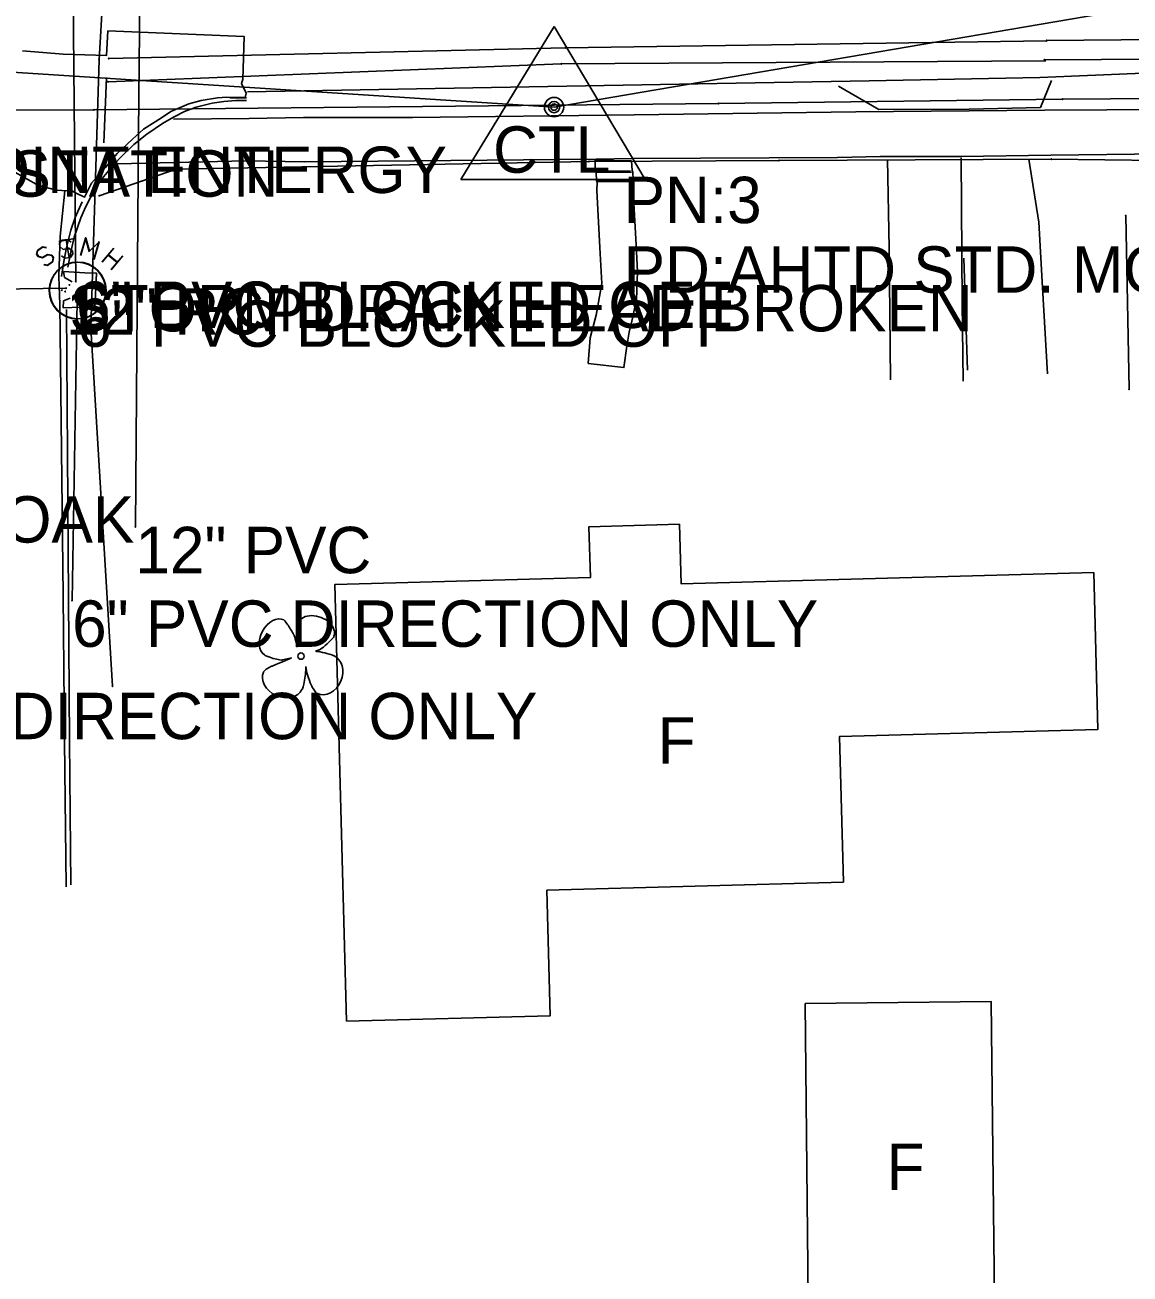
# Model space of a CAD drawing. Extents: x 1304270 to 1306561, y 1876019 to 1876752.
# Drawn here: x 1305936.2 to 1306055.3, y 1876265.9 to 1876400.4 of the extents above; entities that cross this region are included whole.
import ezdxf

# ---------------------------------------------------------------- set-up
doc = ezdxf.new("R2010")
doc.units = 0
for name, color, linetype in [('Default', 7, 'Continuous'), ('S_BUILDING', 7, 'Continuous'), ('S_BUILDING_ANNOT', 7, 'Continuous'), ('S_CURB', 7, 'Continuous'), ('S_DRG_PT_SYM', 7, 'Continuous'), ('S_DRIVEWAY', 7, 'Continuous'), ('S_EDGE_CONCRETE', 7, 'Continuous'), ('S_EDGE_PAVEMENT', 7, 'Continuous'), ('S_FENCE', 7, 'Continuous'), ('S_FIBER_OPTIC_CABLE', 7, 'Continuous'), ('S_GAS_UTILITIES', 7, 'Continuous'), ('S_MANHOLE', 7, 'Continuous'), ('S_MISC_STRUCTURES_ANNOT', 7, 'Continuous'), ('S_MSC_PT_SYM', 7, 'Continuous'), ('S_PRIMARY_CTL', 7, 'Continuous'), ('S_PRIMARY_CTL_ANNOT', 7, 'Continuous'), ('S_SIDEWALK', 7, 'Continuous'), ('S_STORM_SEWER', 7, 'Continuous'), ('S_STORM_SEWER_ANNOT', 7, 'Continuous'), ('S_SURVEY_TEXT_ANNOT', 7, 'Continuous'), ('S_TREE', 7, 'Continuous'), ('S_UTILITY_POLE_ANNOT', 7, 'Continuous'), ('S_UTL_PT_SYM', 7, 'Continuous'), ('S_WATER_UTILITIES', 7, 'Continuous'), ('S_WATER_UTILITIES_ANNOT', 7, 'Continuous')]:
    doc.layers.add(name, color=color, linetype=linetype)

msp = doc.modelspace()

# ---------------------------------------------------------------- linework, layer by layer
at = {"layer": 'Default'}
for p, q in [((1305993.25, 1876391.55), (1306312.09, 1876445.88)), ((1305473.53, 1876424.94), (1305993.25, 1876391.55))]:
    msp.add_line(p, q, dxfattribs=at)
at = {"layer": 'S_BUILDING'}
for points in [[(1306024.44, 1876308.05), (1305992.48, 1876307.19), (1305992.84, 1876293.68), (1305970.9, 1876293.09), (1305969.63, 1876340.14), (1305997.16, 1876340.88), (1305997.01, 1876346.35), (1306006.76, 1876346.61), (1306006.93, 1876340.21), (1306051.4, 1876341.41), (1306051.85, 1876324.52), (1306024.02, 1876323.77)], [(1306020.3, 1876294.98), (1306020.68, 1876259.62), (1306040.74, 1876259.83), (1306040.36, 1876295.2)]]:
    msp.add_lwpolyline(points, close=True, dxfattribs=at)
at = {"layer": 'S_CURB'}
for points in [[(1305960.11, 1876392.26), (1305958.96, 1876392.25), (1305957.65, 1876392.15), (1305956.42, 1876391.97), (1305954.67, 1876391.54), (1305953.41, 1876391.07), (1305952.23, 1876390.48), (1305951.04, 1876389.79), (1305949.38, 1876388.65), (1305947.97, 1876387.54), (1305946.46, 1876386.05), (1305945.64, 1876385.14), (1305944.55, 1876383.85), (1305943.78, 1876382.72), (1305942.79, 1876380.85), (1305942.27, 1876379.63), (1305941.54, 1876377.55), (1305941.22, 1876376.12), (1305940.84, 1876374.32)], [(1305960.1, 1876392.54), (1305958.31, 1876392.55)], [(1305941.17, 1876307.79), (1305941.05, 1876323.28), (1305940.93, 1876338.77), (1305940.82, 1876354.25), (1305940.7, 1876369.74)]]:
    msp.add_lwpolyline(points, dxfattribs=at)
at = {"layer": 'S_DRG_PT_SYM'}
msp.add_lwpolyline([(1305940.22, 1876371.83), (1305940.22, 1876371.88), (1305940.22, 1876371.83), (1305940.17, 1876371.83), (1305940.22, 1876371.83), (1305940.22, 1876371.78), (1305940.22, 1876371.83), (1305940.27, 1876371.83)], dxfattribs=at)
at = {"layer": 'S_DRIVEWAY'}
for points in [[(1306023.91, 1876393.81), (1306028.25, 1876391.29), (1306037.96, 1876391.32), (1306045.65, 1876391.5), (1306046.86, 1876394.43)], [(1306029.18, 1876385.91), (1306029.37, 1876376.36), (1306029.5, 1876362.16)], [(1306037.33, 1876362.02), (1306037.22, 1876370.47), (1306037.11, 1876386.1)], [(1306046.43, 1876362.81), (1306045.89, 1876372.13), (1306045.49, 1876379.16), (1306044.4, 1876385.95)], [(1306037.42, 1876375.28), (1306037.79, 1876363.2)]]:
    msp.add_lwpolyline(points, dxfattribs=at)
at = {"layer": 'S_EDGE_CONCRETE'}
for points in [[(1305934.88, 1876384.67), (1305937.71, 1876383.09), (1305939.63, 1876382.6), (1305941.35, 1876382.5), (1305941.68, 1876382.31), (1305942.65, 1876381.84), (1305943.4, 1876383.36), (1305944.9, 1876385.03), (1305946.16, 1876386.55), (1305947.83, 1876388.09), (1305949.01, 1876389.16), (1305950.94, 1876390.4), (1305951.97, 1876391.06), (1305953.91, 1876391.9), (1305955.21, 1876392.25), (1305957, 1876392.54), (1305957.99, 1876392.62), (1305959.95, 1876392.58), (1305960.09, 1876393.07), (1305959.57, 1876394.08), (1305959.7, 1876394.51), (1305959.85, 1876399.16), (1305952.97, 1876399.46), (1305945.18, 1876399.76), (1305945.02, 1876397.11), (1305940.34, 1876397.25), (1305935.98, 1876397.61)], [(1305944.74, 1876387.69), (1305945.01, 1876394.73)], [(1305997.76, 1876384.7), (1306001.49, 1876384.65)], [(1305997.8, 1876384.51), (1306001.6, 1876384.54)], [(1305997.93, 1876383.61), (1306001.58, 1876383.62)], [(1305998, 1876383.54), (1306001.58, 1876383.55)], [(1305940.39, 1876373.85), (1305942.69, 1876373.71), (1305943.93, 1876373.68), (1305943.77, 1876369.89), (1305942.25, 1876370.01), (1305940.35, 1876369.94), (1305940.39, 1876370.68), (1305941.1, 1876370.98)], [(1305941.31, 1876372.72), (1305940.48, 1876373.2), (1305940.39, 1876373.85)]]:
    msp.add_lwpolyline(points, dxfattribs=at)
msp.add_lwpolyline([(1305997.75, 1876385.84), (1305997.69, 1876385.83), (1305997.69, 1876384.62), (1305997.79, 1876384.51), (1305997.82, 1876383.61), (1305997.88, 1876383.47), (1305997.87, 1876382.57), (1305998.19, 1876376.43), (1305998.41, 1876372.54), (1305997.77, 1876369.13), (1305997.13, 1876366.7), (1305996.93, 1876363.94), (1306000.77, 1876363.49), (1306001.08, 1876365.79), (1306001.34, 1876367.29), (1306001.64, 1876368.5), (1306002.13, 1876370.81), (1306002.24, 1876373.82), (1306002.09, 1876376.7), (1306001.76, 1876382.46), (1306001.77, 1876382.61), (1306001.75, 1876383.55), (1306001.77, 1876383.7), (1306001.72, 1876384.59), (1306001.68, 1876384.72), (1306001.59, 1876385.76)], close=True, dxfattribs=at)
at = {"layer": 'S_EDGE_PAVEMENT'}
for points in [[(1305960.21, 1876393.19), (1305984.49, 1876393.62), (1306008.77, 1876394.06), (1306027.19, 1876394.39), (1306045.6, 1876394.73), (1306057.59, 1876395.26)], [(1305940.55, 1876382.53), (1305940.04, 1876377.65), (1305939.9, 1876373.31), (1305940.01, 1876370.29), (1305940.17, 1876354.61), (1305940.34, 1876338.93), (1305940.5, 1876323.24), (1305940.66, 1876307.56)], [(1305942.41, 1876381.33), (1305941.65, 1876379.66), (1305941.18, 1876378.28), (1305940.71, 1876376.41), (1305940.44, 1876374.92), (1305940.18, 1876373.31)]]:
    msp.add_lwpolyline(points, dxfattribs=at)
at = {"layer": 'S_FENCE'}
msp.add_line((1306055.21, 1876361.15), (1306054.85, 1876379.86), dxfattribs=at)
msp.add_lwpolyline([(1306055.21, 1876361.15), (1306054.85, 1876379.86)], dxfattribs=at)
msp.add_lwpolyline([(1306055.21, 1876361.15), (1306054.85, 1876379.86)], dxfattribs=at)
at = {"layer": 'S_FIBER_OPTIC_CABLE'}
for p, q in [((1305944.24, 1876396.69), (1305946.25, 1876432.14)), ((1306046.32, 1876398.7), (1305994.45, 1876397.92)), ((1306079.65, 1876399.02), (1306046.32, 1876398.72)), ((1306046.32, 1876398.72), (1306046.32, 1876398.7)), ((1305994.45, 1876397.92), (1305945.27, 1876396.78)), ((1305943.35, 1876367.74), (1305944.24, 1876396.69)), ((1305994.03, 1876396.22), (1305945.19, 1876394.27)), ((1306046.18, 1876396.55), (1305994.03, 1876396.22)), ((1306079.49, 1876396.85), (1306046.09, 1876396.66)), ((1306046.09, 1876396.66), (1306046.18, 1876396.55)), ((1305997.01, 1876385.69), (1305952.54, 1876384.85)), ((1306017.5, 1876385.81), (1305997.01, 1876385.69)), ((1306046.82, 1876385.94), (1306017.5, 1876385.81)), ((1306069.93, 1876385.68), (1306046.82, 1876385.94)), ((1305952.54, 1876384.85), (1305944.25, 1876382.01)), ((1305945.68, 1876329.18), (1305943.35, 1876367.74))]:
    msp.add_line(p, q, dxfattribs=at)
at = {"layer": 'S_GAS_UTILITIES'}
for p, q in [((1306048.03, 1876392.4), (1306010.96, 1876391.93)), ((1306078.88, 1876392.59), (1306048.03, 1876392.4)), ((1305943.66, 1876391.26), (1305924.69, 1876391.17)), ((1306010.96, 1876391.93), (1305943.66, 1876391.26))]:
    msp.add_line(p, q, dxfattribs=at)
at = {"layer": 'S_MANHOLE'}
for p, q in [((1305937.57, 1876376.08), (1305937.49, 1876375.69)), ((1305938.11, 1876376.47), (1305937.57, 1876376.08)), ((1305938.54, 1876376.39), (1305938.11, 1876376.47)), ((1305944.55, 1876374.84), (1305945.79, 1876376.31)), ((1305937.49, 1876375.69), (1305937.69, 1876375.42)), ((1305937.69, 1876375.42), (1305938.11, 1876375.3)), ((1305938.11, 1876375.3), (1305938.66, 1876375.65)), ((1305938.66, 1876374.49), (1305938.27, 1876374.57)), ((1305938.66, 1876375.65), (1305939.12, 1876375.58)), ((1305939.2, 1876374.88), (1305938.66, 1876374.49)), ((1305939.12, 1876375.58), (1305939.28, 1876375.3)), ((1305939.28, 1876375.3), (1305939.2, 1876374.88)), ((1305945.21, 1876375.61), (1305946.17, 1876374.8)), ((1305946.76, 1876375.5), (1305945.52, 1876374.03))]:
    msp.add_line(p, q, dxfattribs=at)
for points in [[(1305941.21, 1876377.01), (1305940.87, 1876377.28), (1305940.21, 1876377.2), (1305939.97, 1876376.85), (1305940.01, 1876376.54), (1305940.36, 1876376.23), (1305940.98, 1876376.35), (1305941.37, 1876376.04), (1305941.41, 1876375.73), (1305941.14, 1876375.34), (1305940.52, 1876375.27), (1305940.17, 1876375.54)], [(1305943.66, 1876375.15), (1305944.2, 1876377.01), (1305943.15, 1876376), (1305942.76, 1876377.44), (1305942.22, 1876375.58)]]:
    msp.add_lwpolyline(points, dxfattribs=at)
msp.add_circle((1305941.9, 1876371.78), 3.05, dxfattribs=at)
at = {"layer": 'S_MSC_PT_SYM'}
for points in [[(1306054.85, 1876379.86), (1306054.85, 1876379.91), (1306054.85, 1876379.86), (1306054.8, 1876379.86), (1306054.85, 1876379.86), (1306054.85, 1876379.81), (1306054.85, 1876379.86), (1306054.9, 1876379.86)], [(1305941.03, 1876372.39), (1305941.03, 1876372.44), (1305941.03, 1876372.39), (1305940.97, 1876372.39), (1305941.03, 1876372.39), (1305941.03, 1876372.34), (1305941.03, 1876372.39), (1305941.07, 1876372.39)], [(1306055.21, 1876361.15), (1306055.21, 1876361.2), (1306055.21, 1876361.15), (1306055.16, 1876361.15), (1306055.21, 1876361.15), (1306055.21, 1876361.1), (1306055.21, 1876361.15), (1306055.26, 1876361.15)]]:
    msp.add_lwpolyline(points, dxfattribs=at)
at = {"layer": 'S_PRIMARY_CTL'}
for p, q in [((1305993.25, 1876400.25), (1305983.22, 1876383.74)), ((1305993.25, 1876400.25), (1306003.08, 1876383.74)), ((1305983.22, 1876383.74), (1306003.08, 1876383.74))]:
    msp.add_line(p, q, dxfattribs=at)
for radius in [1.04, 0.609, 0.344]:
    msp.add_circle((1305993.25, 1876391.55), radius, dxfattribs=at)
at = {"layer": 'S_SIDEWALK'}
for points in [[(1305952.26, 1876390.24), (1305960.41, 1876390.32), (1305966.26, 1876390.42), (1305977.98, 1876390.44), (1306001.88, 1876390.73), (1306025.78, 1876391.03), (1306046.11, 1876391.23), (1306059.51, 1876391.31), (1306072.82, 1876391.56), (1306093.38, 1876391.82), (1306107.91, 1876392.05), (1306108.42, 1876392.1), (1306122.83, 1876392.12), (1306134.63, 1876392.34), (1306141.58, 1876392.5), (1306158.19, 1876392.68), (1306174.81, 1876392.86), (1306188.4, 1876393.18)], [(1305946.19, 1876385.43), (1305960.07, 1876385.78), (1305966.36, 1876385.64), (1305978.22, 1876385.78), (1305997.78, 1876385.93), (1306001.65, 1876386), (1306023.78, 1876386.14), (1306028.37, 1876386.22), (1306037.11, 1876386.23), (1306046.79, 1876386.36), (1306058.81, 1876386.53), (1306072.25, 1876386.67), (1306085.1, 1876386.45), (1306093.62, 1876386.85), (1306109.56, 1876387.13), (1306122.97, 1876387.27), (1306134.64, 1876387.44), (1306141.92, 1876387.73), (1306161.2, 1876387.87), (1306180.48, 1876388.02), (1306189.34, 1876388.14)]]:
    msp.add_lwpolyline(points, dxfattribs=at)
at = {"layer": 'S_STORM_SEWER'}
for p, q in [((1305941.01, 1876447.39), (1305941.73, 1876372.76)), ((1305939.89, 1876377.08), (1305941.4, 1876377.35)), ((1305940.66, 1876377.24), (1305941.01, 1876375.3)), ((1305937.6, 1876376.11), (1305937.52, 1876375.73)), ((1305938.14, 1876376.5), (1305937.6, 1876376.11)), ((1305938.57, 1876376.42), (1305938.14, 1876376.5)), ((1305944.57, 1876374.87), (1305945.81, 1876376.35)), ((1305937.52, 1876375.73), (1305937.72, 1876375.46)), ((1305937.72, 1876375.46), (1305938.14, 1876375.34)), ((1305938.14, 1876375.34), (1305938.68, 1876375.69)), ((1305938.68, 1876374.53), (1305938.3, 1876374.6)), ((1305938.68, 1876375.69), (1305939.15, 1876375.61)), ((1305939.23, 1876374.91), (1305938.68, 1876374.53)), ((1305939.15, 1876375.61), (1305939.3, 1876375.34)), ((1305939.3, 1876375.34), (1305939.23, 1876374.91)), ((1305945.23, 1876375.65), (1305946.2, 1876374.84)), ((1305946.78, 1876375.53), (1305945.54, 1876374.06)), ((1305940.67, 1876372.04), (1305908.55, 1876371.55)), ((1305941.32, 1876338.41), (1305941.86, 1876370.73))]:
    msp.add_line(p, q, dxfattribs=at)
msp.add_lwpolyline([(1305943.68, 1876375.18), (1305944.23, 1876377.04), (1305943.18, 1876376.04), (1305942.79, 1876377.47), (1305942.25, 1876375.61)], dxfattribs=at)
msp.add_circle((1305941.93, 1876371.81), 3.05, dxfattribs=at)
at = {"layer": 'S_TREE'}
for p, q in [((1305965.61, 1876333.39), (1305965.37, 1876334.28)), ((1305967.56, 1876332.93), (1305967.94, 1876333.09)), ((1305964.96, 1876332.23), (1305963.99, 1876332.01)), ((1305966.5, 1876331.3), (1305966.57, 1876330.86))]:
    msp.add_line(p, q, dxfattribs=at)
msp.add_circle((1305965.98, 1876332.41), 0.341, dxfattribs=at)
for centre, major_axis, ratio, start_param, end_param in [((1305967.64, 1876335.3), (1.89, -0.74), 0.673998, 0, 3.141593), ((1305963.09, 1876334.43), (-1.03, -1.88), 0.662338, 3.141593, 6.283185), ((1305964.74, 1876335.3), (0.62, -1.01), 0.083512, 0, 3.141593), ((1305965.68, 1876334.72), (-0.07, -1.33), 0.068203, 3.141593, 6.283185), ((1305968.74, 1876333.82), (-0.798, -0.73), 0.092159, 0, 3.141593), ((1305968.52, 1876332.7), (0.96, -0.23), 0.056001, 0, 3.141593), ((1305963.02, 1876332.28), (0.964, -0.267), 0.113563, 3.141593, 6.283185), ((1305963.92, 1876331.78), (1.04, 0.44), 0.002756, 3.141593, 6.283185), ((1305968.6, 1876330.42), (0.88, 2.05), 0.81717, 3.141593, 6.283185), ((1305964, 1876329.75), (2.07, -0.93), 0.760068, 3.141593, 6.283185), ((1305962.41, 1876331.01), (0.477, 0.328), 0.136309, 0, 3.141593), ((1305966.26, 1876330.13), (0.19, 1.31), 0.114148, 3.141593, 5.822668), ((1305966.83, 1876330.09), (0.254, -0.771), 0.051603, 3.141593, 6.283185), ((1305967.4, 1876328.85), (-0.321, 0.467), 0.094289, 0, 3.141593)]:
    msp.add_ellipse(centre, major_axis=major_axis, ratio=ratio, start_param=start_param, end_param=end_param, dxfattribs=at)
at = {"layer": 'S_UTL_PT_SYM'}
for points in [[(1306046.32, 1876398.72), (1306046.32, 1876398.77), (1306046.32, 1876398.72), (1306046.27, 1876398.72), (1306046.32, 1876398.72), (1306046.32, 1876398.67), (1306046.32, 1876398.72), (1306046.37, 1876398.72)], [(1306046.32, 1876398.7), (1306046.32, 1876398.75), (1306046.32, 1876398.7), (1306046.27, 1876398.7), (1306046.32, 1876398.7), (1306046.32, 1876398.65), (1306046.32, 1876398.7), (1306046.37, 1876398.7)], [(1305994.45, 1876397.92), (1305994.45, 1876397.97), (1305994.45, 1876397.92), (1305994.4, 1876397.92), (1305994.45, 1876397.92), (1305994.45, 1876397.87), (1305994.45, 1876397.92), (1305994.5, 1876397.92)], [(1305944.24, 1876396.69), (1305944.24, 1876396.74), (1305944.24, 1876396.69), (1305944.19, 1876396.69), (1305944.24, 1876396.69), (1305944.24, 1876396.64), (1305944.24, 1876396.69), (1305944.29, 1876396.69)], [(1305945.27, 1876396.78), (1305945.27, 1876396.83), (1305945.27, 1876396.78), (1305945.22, 1876396.78), (1305945.27, 1876396.78), (1305945.27, 1876396.73), (1305945.27, 1876396.78), (1305945.32, 1876396.78)], [(1305994.03, 1876396.22), (1305994.03, 1876396.27), (1305994.03, 1876396.22), (1305993.98, 1876396.22), (1305994.03, 1876396.22), (1305994.03, 1876396.17), (1305994.03, 1876396.22), (1305994.08, 1876396.22)], [(1306046.09, 1876396.66), (1306046.09, 1876396.71), (1306046.09, 1876396.66), (1306046.04, 1876396.66), (1306046.09, 1876396.66), (1306046.09, 1876396.61), (1306046.09, 1876396.66), (1306046.14, 1876396.66)], [(1306046.18, 1876396.55), (1306046.18, 1876396.6), (1306046.18, 1876396.55), (1306046.13, 1876396.55), (1306046.18, 1876396.55), (1306046.18, 1876396.5), (1306046.18, 1876396.55), (1306046.23, 1876396.55)], [(1305945.19, 1876394.27), (1305945.19, 1876394.32), (1305945.19, 1876394.27), (1305945.14, 1876394.27), (1305945.19, 1876394.27), (1305945.19, 1876394.22), (1305945.19, 1876394.27), (1305945.24, 1876394.27)], [(1306010.96, 1876391.93), (1306010.96, 1876391.98), (1306010.96, 1876391.93), (1306010.91, 1876391.93), (1306010.96, 1876391.93), (1306010.96, 1876391.88), (1306010.96, 1876391.93), (1306011.01, 1876391.93)], [(1306048.03, 1876392.4), (1306048.03, 1876392.45), (1306048.03, 1876392.4), (1306047.98, 1876392.4), (1306048.03, 1876392.4), (1306048.03, 1876392.35), (1306048.03, 1876392.4), (1306048.08, 1876392.4)], [(1305943.66, 1876391.26), (1305943.66, 1876391.31), (1305943.66, 1876391.26), (1305943.61, 1876391.26), (1305943.66, 1876391.26), (1305943.66, 1876391.21), (1305943.66, 1876391.26), (1305943.71, 1876391.26)], [(1305948.48, 1876388.8), (1305948.48, 1876388.85), (1305948.48, 1876388.8), (1305948.43, 1876388.8), (1305948.48, 1876388.8), (1305948.48, 1876388.75), (1305948.48, 1876388.8), (1305948.53, 1876388.8)], [(1305997.01, 1876385.69), (1305997.01, 1876385.74), (1305997.01, 1876385.69), (1305996.96, 1876385.69), (1305997.01, 1876385.69), (1305997.01, 1876385.64), (1305997.01, 1876385.69), (1305997.06, 1876385.69)], [(1306017.5, 1876385.81), (1306017.5, 1876385.86), (1306017.5, 1876385.81), (1306017.45, 1876385.81), (1306017.5, 1876385.81), (1306017.5, 1876385.76), (1306017.5, 1876385.81), (1306017.55, 1876385.81)], [(1306046.82, 1876385.94), (1306046.82, 1876385.99), (1306046.82, 1876385.94), (1306046.77, 1876385.94), (1306046.82, 1876385.94), (1306046.82, 1876385.89), (1306046.82, 1876385.94), (1306046.87, 1876385.94)], [(1305952.54, 1876384.85), (1305952.54, 1876384.9), (1305952.54, 1876384.85), (1305952.49, 1876384.85), (1305952.54, 1876384.85), (1305952.54, 1876384.8), (1305952.54, 1876384.85), (1305952.59, 1876384.85)], [(1305944.25, 1876382.01), (1305944.25, 1876382.06), (1305944.25, 1876382.01), (1305944.2, 1876382.01), (1305944.25, 1876382.01), (1305944.25, 1876381.96), (1305944.25, 1876382.01), (1305944.3, 1876382.01)], [(1305940.67, 1876372.04), (1305940.67, 1876372.09), (1305940.67, 1876372.04), (1305940.62, 1876372.04), (1305940.67, 1876372.04), (1305940.67, 1876371.99), (1305940.67, 1876372.04), (1305940.72, 1876372.04)], [(1305941.73, 1876372.76), (1305941.73, 1876372.81), (1305941.73, 1876372.76), (1305941.68, 1876372.76), (1305941.73, 1876372.76), (1305941.73, 1876372.71), (1305941.73, 1876372.76), (1305941.78, 1876372.76)], [(1305940.58, 1876371.68), (1305940.58, 1876371.73), (1305940.58, 1876371.68), (1305940.53, 1876371.68), (1305940.58, 1876371.68), (1305940.58, 1876371.63), (1305940.58, 1876371.68), (1305940.63, 1876371.68)], [(1305941.86, 1876370.73), (1305941.86, 1876370.78), (1305941.86, 1876370.73), (1305941.81, 1876370.73), (1305941.86, 1876370.73), (1305941.86, 1876370.68), (1305941.86, 1876370.73), (1305941.91, 1876370.73)], [(1305943.35, 1876367.74), (1305943.35, 1876367.79), (1305943.35, 1876367.74), (1305943.3, 1876367.74), (1305943.35, 1876367.74), (1305943.35, 1876367.69), (1305943.35, 1876367.74), (1305943.4, 1876367.74)], [(1305948.14, 1876346.34), (1305948.14, 1876346.39), (1305948.14, 1876346.34), (1305948.09, 1876346.34), (1305948.14, 1876346.34), (1305948.14, 1876346.29), (1305948.14, 1876346.34), (1305948.19, 1876346.34)], [(1305941.32, 1876338.41), (1305941.32, 1876338.46), (1305941.32, 1876338.41), (1305941.27, 1876338.41), (1305941.32, 1876338.41), (1305941.32, 1876338.36), (1305941.32, 1876338.41), (1305941.37, 1876338.41)], [(1305945.68, 1876329.18), (1305945.68, 1876329.23), (1305945.68, 1876329.18), (1305945.63, 1876329.18), (1305945.68, 1876329.18), (1305945.68, 1876329.13), (1305945.68, 1876329.18), (1305945.73, 1876329.18)]]:
    msp.add_lwpolyline(points, dxfattribs=at)
at = {"layer": 'S_WATER_UTILITIES'}
for p, q in [((1305948.48, 1876388.8), (1305948.87, 1876426.5)), ((1305948.14, 1876346.34), (1305948.48, 1876388.8))]:
    msp.add_line(p, q, dxfattribs=at)

# ---------------------------------------------------------------- texts
at = {"layer": 'S_BUILDING_ANNOT'}
for p in [(1306004.42, 1876320.83), (1306029.08, 1876274.91)]:
    msp.add_text('F', height=5, dxfattribs=at).set_placement(p)
at = {"layer": 'S_MISC_STRUCTURES_ANNOT'}
msp.add_text('GAS TEST STATION', height=5, dxfattribs=at).set_placement((1305899.64, 1876381.9))
at = {"layer": 'S_PRIMARY_CTL'}
msp.add_text('CTL', height=5, rotation=360, dxfattribs=at).set_placement((1305986.67, 1876384.48))
at = {"layer": 'S_PRIMARY_CTL_ANNOT'}
for s, p in [('PN:3', (1306000.75, 1876379.05)), ('PD:AHTD STD. MONUMENT STAMPED PN:3', (1306000.75, 1876371.55))]:
    msp.add_text(s, height=5, dxfattribs=at).set_placement(p)
at = {"layer": 'S_STORM_SEWER_ANNOT'}
for s, p in [('12" RCP', (1305940.67, 1876367.04)), ('6" PVC BLOCKED OFF', (1305941.73, 1876367.76)), ('6" PVC BLOCKED OFF', (1305941.86, 1876365.73)), ('6" PVC DIRECTION ONLY', (1305941.32, 1876333.41)), ('12" RCP DIRECTION ONLY', (1305906.97, 1876323.46))]:
    msp.add_text(s, height=5, dxfattribs=at).set_placement(p)
at = {"layer": 'S_SURVEY_TEXT_ANNOT'}
msp.add_text('STORM DRAIN HEAD BROKEN', height=5, dxfattribs=at).set_placement((1305941.03, 1876367.39))
at = {"layer": 'S_UTILITY_POLE_ANNOT'}
for s, p in [('CENTERPOINT ENTERGY', (1305899.62, 1876382.3)), ('28" WHITE OAK', (1305898.83, 1876344.64))]:
    msp.add_text(s, height=5, dxfattribs=at).set_placement(p)
at = {"layer": 'S_WATER_UTILITIES_ANNOT'}
msp.add_text('12" PVC', height=5, dxfattribs=at).set_placement((1305948.14, 1876341.34))

doc.saveas('drawing.dxf')
